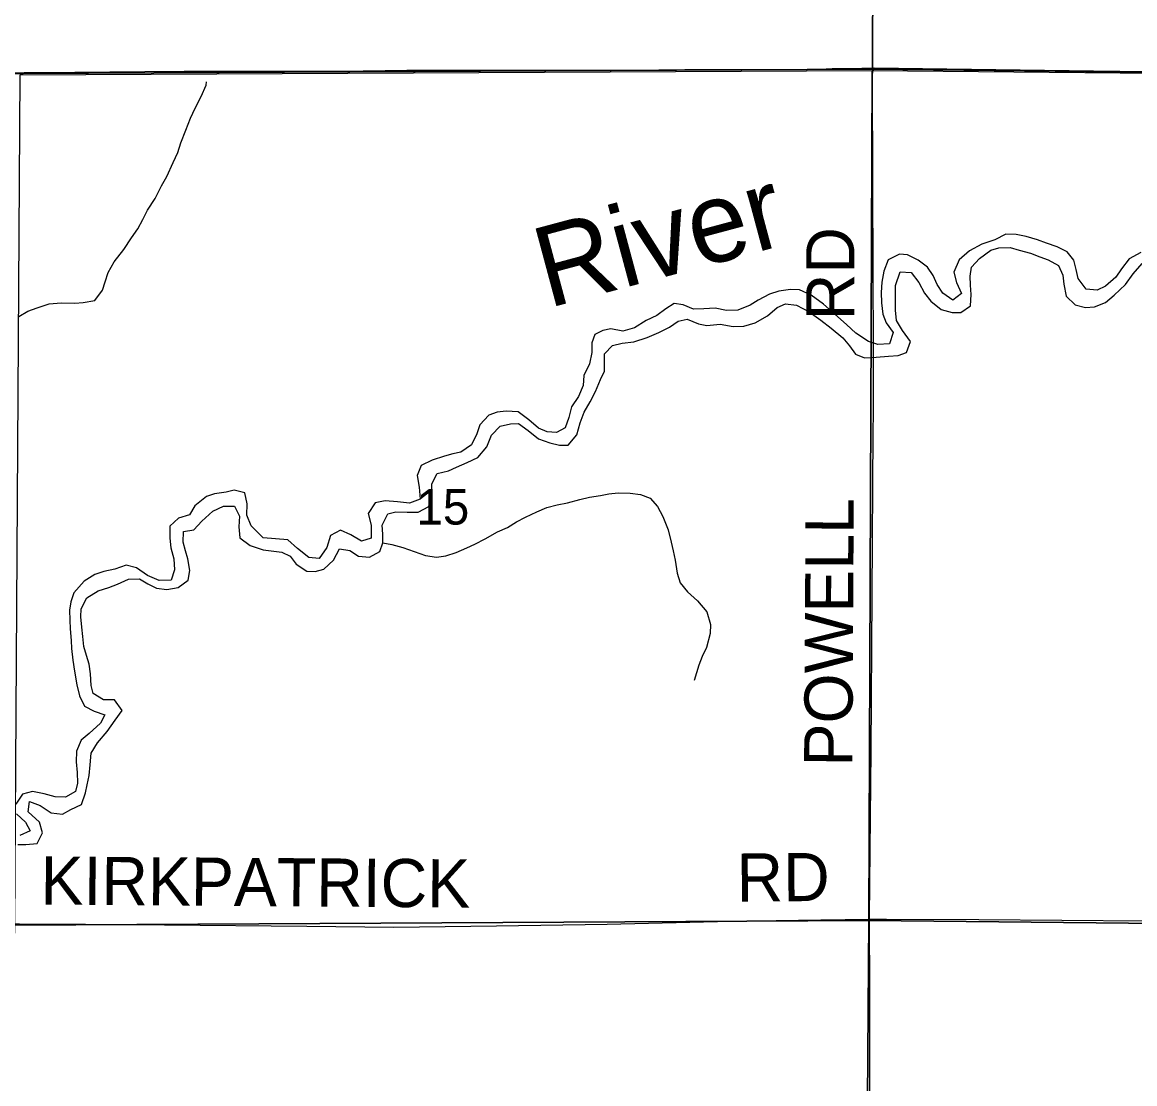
# Model space of a CAD drawing. Extents: x 1584893 to 1934202, y 663575 to 1091909.
# Drawn here: x 1793649 to 1800576, y 978799 to 985411 of the extents above; entities that cross this region are included whole.
import ezdxf

# ---------------------------------------------------------------- set-up
doc = ezdxf.new("R2010")
doc.units = 0
for name, color, linetype in [('GM_X_Adjacent_County', 7, 'Continuous'), ('GM_X_County', 7, 'Continuous'), ('GM_X_County_Road', 7, 'Continuous'), ('GM_X_County_Road_Text', 7, 'Continuous'), ('GM_X_Major_River', 7, 'Continuous'), ('GM_X_Major_River_Text', 7, 'Continuous'), ('GM_X_Minor_River', 7, 'Continuous'), ('GM_X_Section', 7, 'Continuous'), ('GM_X_Section_Text', 7, 'Continuous'), ('GM_X_Township', 7, 'Continuous'), ('GM_X_Township_Road', 7, 'Continuous'), ('GM_X_Township_Road_Text', 7, 'Continuous')]:
    doc.layers.add(name, color=color, linetype=linetype)

msp = doc.modelspace()

# ---------------------------------------------------------------- linework, layer by layer
at = {"layer": 'GM_X_Adjacent_County'}
for points in [[(1798963, 1000817.5), (1798919.4, 995550.1), (1798958.2, 993982), (1798960.7, 990391.9), (1798944.1, 985118.7), (1793655.1, 985091.4), (1790446.1, 985072.3), (1788294.4, 985062.9), (1785879.4, 985048.8), (1785146.5, 985037.7), (1784945.3, 985034.8), (1783032.3, 985018.6), (1777599.8, 984995.7), (1776296.6, 985001.4), (1772301.8, 985036.8), (1771919.4, 985044.5), (1771011.6, 985062.3), (1767040.7, 985145.4), (1761102.7, 985171.2), (1756190.2, 985192.4)], [(1810918.2, 985032.9), (1809553.9, 985051.1), (1805633.6, 985059.6), (1804716.7, 985058.2), (1804440.3, 985060.6), (1804246.1, 985060.1), (1798944.1, 985118.7), (1798960.7, 990391.9), (1798958.2, 993982), (1798919.4, 995550.1), (1798963, 1000817.5)]]:
    msp.add_lwpolyline(points, dxfattribs=at)
at = {"layer": 'GM_X_County'}
msp.add_lwpolyline([(1756190.2, 985192.4), (1761102.7, 985171.2), (1767040.7, 985145.4), (1771011.6, 985062.3), (1771919.4, 985044.5), (1772301.8, 985036.8), (1776296.6, 985001.4), (1777599.8, 984995.7), (1783032.3, 985018.6), (1784945.3, 985034.8), (1785146.5, 985037.7), (1785879.4, 985048.8), (1788294.4, 985062.9), (1790446.1, 985072.3), (1793655.1, 985091.4), (1798944.1, 985118.7), (1804246.1, 985060.1), (1804440.3, 985060.6), (1804716.7, 985058.2), (1805633.6, 985059.6), (1809553.9, 985051.1), (1810918.2, 985032.9)], dxfattribs=at)
at = {"layer": 'GM_X_County_Road'}
for points in [[(1790514.2, 979812.8), (1790957.4, 979819.1), (1791417, 979818.3), (1791958.8, 979812.3), (1792500.1, 979806.5), (1793238.6, 979798.9), (1793632.5, 979795.2), (1794042.8, 979792.3), (1794535.1, 979788.9), (1795421.3, 979779.9), (1795962.8, 979775.5), (1796602.7, 979782.8), (1797291.9, 979794), (1798063.1, 979811), (1798621, 979820.2), (1798925.1, 979823.4)], [(1798925.1, 979823.4), (1799031.3, 979824.5), (1799605.8, 979821.8), (1800639.7, 979814.1), (1801000.7, 979811.3), (1801493.1, 979807.3), (1802559.8, 979796.2), (1804053.2, 979779), (1804213.8, 979777.6)]]:
    msp.add_lwpolyline(points, dxfattribs=at)
at = {"layer": 'GM_X_Major_River'}
for points in [[(1800341.9, 983741.7), (1800273.9, 983748.5), (1800224.6, 983815.3), (1800211.3, 983871.6), (1800195.9, 983928), (1800154.5, 983980.6), (1800092.8, 984011.4), (1800026.9, 984034.2), (1799971.1, 984055), (1799899.2, 984075.9), (1799837.3, 984088.6), (1799773.2, 984091.4), (1799704.7, 984056.1), (1799624.3, 984028.9), (1799547.7, 983987.7), (1799482.9, 983930.3), (1799450, 983854.5), (1799467.2, 983790.1), (1799496.5, 983721.5), (1799443.9, 983680), (1799380.3, 983722.9), (1799346.9, 983777.4), (1799321.5, 983833.9), (1799286.1, 983884.5), (1799228.5, 983929.3), (1799160.8, 983962.2), (1799110.8, 983966.8), (1799040.3, 983931.5), (1799013.4, 983859.6), (1799000.6, 983791.5), (1798997.8, 983727.4), (1798999.1, 983663.2), (1799008.2, 983592.8), (1799027.6, 983538.5), (1799071, 983477.8), (1799050.1, 983407.8), (1798975.9, 983402.7), (1798918.1, 983421.4), (1798840.6, 983474.5), (1798781.1, 983527.3), (1798709.8, 983592.3), (1798638.4, 983655.4), (1798561, 983710.4), (1798489.3, 983743.4), (1798433.2, 983746), (1798361, 983736.8), (1798302.7, 983717.5), (1798232.1, 983680.2), (1798181.7, 983648.7), (1798105.2, 983617.5), (1798035.1, 983616.3), (1797963.2, 983629.2), (1797893, 983626), (1797828.9, 983622.7), (1797765.1, 983651.6), (1797709.1, 983658.2), (1797656.7, 983626.8), (1797600.1, 983585.3), (1797533.6, 983554), (1797461, 983506.7), (1797388.6, 983487.5), (1797314.7, 983500.4), (1797264.5, 983490.9), (1797214.1, 983465.4), (1797195.5, 983413.5), (1797196.8, 983353.3), (1797181.9, 983283.3), (1797145, 983211.5), (1797142.3, 983147.3), (1797113.4, 983079.5), (1797068.6, 983015.8), (1797051.8, 982949.8), (1797029, 982883.9), (1796976.6, 982856.4), (1796918.5, 982859.1), (1796864.7, 982881.8), (1796803.3, 982934.7), (1796737.7, 982983.6), (1796661.7, 982988.5), (1796605.5, 982983.1), (1796555.2, 982963.7), (1796498.5, 982904.1), (1796479.7, 982846.2), (1796446.9, 982778.4), (1796380.3, 982733), (1796330.1, 982723.6), (1796277.8, 982708.1), (1796201.4, 982682.9), (1796132.9, 982649.7), (1796108.1, 982587.8), (1796121.3, 982515.4), (1796126.4, 982441.1), (1796060, 982415.8), (1795986, 982422.7), (1795910, 982429.6), (1795845.8, 982418.3), (1795802.9, 982350.6), (1795822.1, 982278.2), (1795821.1, 982197.9), (1795760.8, 982178.6), (1795695.2, 982217.5)], [(1795811.7, 982079.7), (1795876.2, 982115), (1795894.9, 982169), (1795895.5, 982223.1), (1795890.2, 982277.4), (1795925.1, 982349.2), (1795975.3, 982360.6), (1796045.4, 982359.8), (1796115.4, 982359), (1796180, 982394.3), (1796196.8, 982464.3), (1796199.7, 982536.5), (1796232.5, 982600.3), (1796302.8, 982617.6), (1796353.1, 982639), (1796419.5, 982668.4), (1796486, 982699.7), (1796542.9, 982767.2), (1796571.8, 982839.1), (1796624.5, 982894.6), (1796688.8, 982909.9), (1796738.9, 982911.3), (1796798.5, 982868.5), (1796863.9, 982815.6), (1796933.7, 982790.7), (1796993.7, 982776), (1797047.7, 982777.3), (1797102.6, 982840.9), (1797123.5, 982914.9), (1797148.3, 982982.8), (1797185.1, 983046.5), (1797217.9, 983110.3), (1797248.9, 983186.2), (1797275.5, 983238), (1797274.1, 983288.2), (1797274.8, 983346.4), (1797325.5, 983397.9), (1797385.7, 983411.3), (1797458, 983420.5), (1797540.4, 983447.6), (1797612.9, 983478.8), (1797679.4, 983512.2), (1797733.9, 983549.6), (1797790.1, 983561), (1797859.9, 983532.1), (1797911.8, 983521.5), (1797994, 983530.5), (1798076, 983515.5), (1798142.1, 983518.8), (1798212.4, 983538), (1798289.1, 983583.2), (1798349.8, 983634.7), (1798402.1, 983656.1), (1798470.1, 983649.3), (1798549.7, 983606.3), (1798621.2, 983555.3), (1798686.7, 983504.4), (1798758.1, 983445.3), (1798799.6, 983394.7), (1798837, 983344.1), (1798892.9, 983321.4), (1798967, 983324.5), (1799043.2, 983331.7), (1799103.3, 983335), (1799155.6, 983354.4), (1799180.5, 983422.3), (1799129.2, 983491.1), (1799091.9, 983553.8), (1799086.6, 983618), (1799087.2, 983668.2), (1799085.9, 983720.3), (1799086.5, 983770.5), (1799115.5, 983856.4), (1799183.6, 983851.6), (1799230.9, 983788.8), (1799266.2, 983724.2), (1799305.6, 983673.6), (1799371.1, 983620.7), (1799439, 983603.8), (1799493.1, 983603.2), (1799553.6, 983644.6), (1799558.5, 983714.8), (1799553.2, 983773), (1799551.8, 983829.2), (1799560.5, 983885.3), (1799609.2, 983938.8), (1799679.9, 983990.2), (1799730.2, 984005.6), (1799800.3, 984006.8), (1799856.2, 983992.1), (1799926.1, 983973.2), (1799985.9, 983950.5), (1800037.7, 983931.8), (1800101.4, 983895), (1800128.7, 983834.5), (1800134.1, 983780.2), (1800149.2, 983703.8), (1800204.7, 983651), (1800268.6, 983634.2), (1800324.7, 983637.6), (1800393.1, 983664.9)], [(1800613.1, 983977.2), (1800540.5, 983938), (1800493.7, 983874.3), (1800459.1, 983822.6), (1800394.3, 983767.2), (1800341.9, 983741.7)], [(1800393.1, 983664.9), (1800447.7, 983710.4), (1800518.6, 983777.7), (1800565.5, 983843.4), (1800622.3, 983908.9)], [(1795150.3, 982198.8), (1795075.5, 982274.8), (1795048, 982341.1), (1795050.5, 982411.2), (1795035, 982479.5), (1794969.1, 982496), (1794918.9, 982484.3), (1794846.8, 982472.8), (1794796.6, 982457.1), (1794724.1, 982399.5), (1794691.7, 982343.6), (1794621.4, 982322), (1794569, 982272.3), (1794568.5, 982198.1), (1794574, 982138), (1794593.5, 982069.7), (1794597, 981999.5), (1794576.5, 981935.5), (1794502.4, 981934), (1794428.6, 981964.6), (1794360.9, 982013.2), (1794297, 982029.7), (1794226.7, 982004.1), (1794156.5, 981990.6), (1794102.3, 981970.9), (1794034, 981929.3), (1793971.4, 981857.6), (1793952.9, 981801.6), (1793944.5, 981749.5), (1793946.1, 981687.4), (1793947.7, 981633.2), (1793953.1, 981561), (1793956.8, 981510.9), (1793964.2, 981436.7), (1793975.7, 981368.5), (1793989.1, 981284.2), (1794006.6, 981215.9), (1794036.2, 981151.6), (1794098, 981119.1), (1794163.9, 981096.6), (1794137.5, 981044.6), (1794066.9, 980981), (1794016.6, 980939.2), (1793988, 980871.3), (1793985.5, 980805.2), (1793991, 980737), (1793992.6, 980670.8), (1793980.2, 980618.8), (1793917.8, 980583.2), (1793853.8, 980585.6), (1793785.9, 980604.1), (1793713.9, 980618.7), (1793651.7, 980603.1), (1793609.2, 980541.2)], [(1793621.4, 980288.6), (1793671.4, 980290.2), (1793741.5, 980295.8), (1793776, 980361.7), (1793756.5, 980427.9), (1793686.9, 980492.6), (1793695.4, 980556.7), (1793761.3, 980532.1), (1793829, 980487.6), (1793901, 980479), (1793951.3, 980506.8), (1794017.6, 980538.4), (1794044.1, 980610.3), (1794054.5, 980660.4), (1794065, 980718.4), (1794071.5, 980786.5), (1794078, 980858.7), (1794118.5, 980922.5), (1794179.1, 980992.2), (1794227.7, 981064.1), (1794272.2, 981123.9), (1794224.6, 981190.3), (1794154.6, 981190.8), (1794090.8, 981229.4), (1794079.2, 981279.6), (1794073.7, 981351.8), (1794066.1, 981411.9), (1794048.5, 981466.2), (1794032.9, 981522.4), (1794027.4, 981584.6), (1794019.8, 981642.8), (1794014.3, 981706.9), (1794016.7, 981757), (1794051.2, 981824.9), (1794121.6, 981868.5), (1794187.8, 981890.1), (1794242, 981911.8), (1794310.3, 981941.4), (1794378.4, 981944.9), (1794432.2, 981912.5), (1794486.1, 981886), (1794550.1, 981877.6), (1794620.2, 981891.1), (1794682.6, 981936.8), (1794693.1, 981996.8), (1794679.6, 982069.1), (1794666, 982119.3), (1794650.3, 982173.5), (1794652.9, 982239.7), (1794717, 982249.2), (1794767.4, 982303), (1794836, 982366.6), (1794902.2, 982396.2), (1794970.3, 982395.8), (1795001.9, 982335.4), (1794997.4, 982267.3), (1795004.9, 982199.1), (1795068.6, 982152.6), (1795148.8, 982125.1)], [(1795695.2, 982217.5), (1795631.4, 982246.3), (1795569, 982214.9), (1795546, 982139), (1795497.2, 982071.3), (1795433.1, 982076.1), (1795363.7, 982133.1), (1795302.2, 982186), (1795150.3, 982198.8)], [(1795148.8, 982125.1), (1795265.3, 982110.2), (1795317.1, 982085.5), (1795354.5, 982034.9), (1795422.1, 981992), (1795472.2, 981989.4), (1795526.4, 982004.8), (1795587.1, 982060.3), (1795624.1, 982132), (1795688, 982121.3), (1795743.7, 982084.5), (1795811.7, 982079.7)], [(1793612.8, 980481.1), (1793670.5, 980428.5), (1793698.1, 980374.2), (1793633.8, 980344.6)]]:
    msp.add_lwpolyline(points, dxfattribs=at)
at = {"layer": 'GM_X_Minor_River'}
for points in [[(1793627.9, 983577.7), (1793684.2, 983611.3), (1793742.4, 983633), (1793816.6, 983656.5), (1793892.7, 983664), (1793976.8, 983661.4), (1794028.9, 983665.1), (1794101.1, 983678.6), (1794149.6, 983742.4), (1794166, 983794.4), (1794184.4, 983852.4), (1794221, 983918.3), (1794281.6, 983996), (1794330.2, 984067.8), (1794368.6, 984123.7), (1794401.1, 984181.6), (1794429.5, 984239.5), (1794476.1, 984313.3), (1794516.7, 984391.2), (1794549.2, 984449.1), (1794589.9, 984537), (1794618.4, 984598.9), (1794636.9, 984658.9), (1794667.5, 984738.9), (1794696.1, 984812.8), (1794726.5, 984874.8), (1794763.1, 984948.7), (1794793.7, 985018.6), (1794797.1, 985039.8)], [(1795894.9, 982169), (1795950.8, 982158.3), (1796018.7, 982139.4), (1796090.5, 982114.5), (1796160.3, 982089.7), (1796228.3, 982078.8), (1796286.5, 982088.2), (1796350.8, 982107.5), (1796417.3, 982136.8), (1796467.6, 982160.3), (1796532.1, 982193.6), (1796608.7, 982236.8), (1796671.1, 982264.2), (1796727.6, 982299.7), (1796782.1, 982329.1), (1796852.5, 982360.4), (1796914.9, 982387.7), (1796979.2, 982405), (1797043.5, 982418.3), (1797121.8, 982437.4), (1797182.1, 982452.8), (1797250.3, 982464), (1797302.5, 982473.4), (1797360.7, 982478.8), (1797434.8, 982477.9), (1797498.8, 982469.2), (1797558.6, 982446.4), (1797604, 982393.7), (1797637.3, 982333.1), (1797670.4, 982248.5), (1797689.5, 982172), (1797702.9, 982117.7), (1797714.2, 982059.4), (1797727.3, 981979), (1797746.6, 981918.6), (1797792, 981863.9), (1797853.4, 981807), (1797912.7, 981738.1), (1797933.8, 981659.6), (1797933.2, 981603.5), (1797910.1, 981515.5), (1797883.4, 981459.6), (1797862.7, 981405.7), (1797833.6, 981311.8)]]:
    msp.add_lwpolyline(points, dxfattribs=at)
at = {"layer": 'GM_X_Section'}
for points in [[(1798941.7, 985111.2), (1798921.1, 979816.2), (1793602.5, 979786.3), (1793636.7, 985083.2)], [(1798941.7, 985111.2), (1804234.6, 985059.6), (1804175.9, 979761.7), (1798921.1, 979816.2)], [(1793602.5, 979786.3), (1798921.1, 979816.2), (1798880.2, 974507.2), (1793492.3, 974493.9)], [(1798921.1, 979816.2), (1804175.9, 979761.7), (1804173.2, 974476.5), (1798880.2, 974507.2)]]:
    msp.add_lwpolyline(points, close=True, dxfattribs=at)
at = {"layer": 'GM_X_Township'}
msp.add_lwpolyline([(1783032.3, 985018.6), (1784945.3, 985034.8), (1785146.5, 985037.7), (1785879.4, 985048.8), (1788294.4, 985062.9), (1790446.1, 985072.3), (1793655.1, 985091.4), (1798944.1, 985118.7), (1804246.1, 985060.1), (1804440.3, 985060.6), (1804716.7, 985058.2), (1805633.6, 985059.6), (1809553.9, 985051.1), (1809489.7, 979763.3), (1809470.3, 974481.1), (1809409.4, 966524.3)], dxfattribs=at)
at = {"layer": 'GM_X_Township_Road'}
for points in [[(1790448.7, 985077.4), (1790503.7, 985078), (1790851.5, 985080.6), (1791060.9, 985081.7), (1791234.2, 985084), (1791371.5, 985085.1), (1791538.3, 985086.2), (1791749.8, 985086.3), (1791918.8, 985087.4), (1792081.2, 985088.5), (1792183.7, 985089.6), (1792386.4, 985090.8), (1792607.7, 985090.8), (1793100.5, 985093.1), (1793428.6, 985095.4), (1793662, 985097.3)], [(1793662, 985097.3), (1793975.8, 985099.9), (1794411.9, 985103.3), (1794657.2, 985106.6), (1794869.4, 985106.8), (1795017.1, 985106), (1795230.6, 985105.6), (1795509.5, 985106.5), (1795772.2, 985107.9), (1796044.9, 985111.3), (1796573.6, 985112.5), (1796919.2, 985112.6), (1797199.4, 985112.7), (1797451.2, 985112.7), (1797774.9, 985116.1), (1797964.6, 985116.1), (1798299.9, 985116.2), (1798541.3, 985119.5), (1798654.4, 985120.4), (1798693.1, 985121.8), (1798795, 985123.4), (1798955.8, 985126.6)], [(1798949.6, 983379.8), (1798947.1, 983858.7), (1798945.2, 984400.1), (1798943.1, 985070.5), (1798944.2, 985085.9), (1798945.2, 985100), (1798947.8, 985111.2), (1798951.7, 985120.2), (1798955.8, 985126.6)], [(1798955.8, 985126.6), (1799254.8, 985122.9), (1800319.5, 985108.4), (1800810.4, 985101.5), (1800941.6, 985100.4), (1801352.3, 985096.8), (1801598.7, 985094), (1802173.7, 985088.9), (1802436.6, 985086.8), (1802962.4, 985084.2), (1803675.3, 985073.1), (1803882, 985069.9), (1804248.7, 985067.6)], [(1798925.1, 979823.4), (1798925, 979839.1), (1798934.5, 980872.7), (1798941.1, 981840.7), (1798948.2, 982857.9), (1798949.7, 982977.7), (1798950.4, 983218.9), (1798949.6, 983379.8)], [(1798948, 978516.4), (1798946.3, 978517.6), (1798940, 978523.5), (1798935.5, 978529.3), (1798931.2, 978536.1), (1798928, 978543.4), (1798925.8, 978551.5), (1798924.2, 978560.8), (1798923.4, 978570.5), (1798923.1, 978592), (1798924.2, 978666.3), (1798926.3, 978756.2), (1798927.7, 979379.7), (1798925.1, 979823.4)]]:
    msp.add_lwpolyline(points, dxfattribs=at)

# ---------------------------------------------------------------- texts
at = {"layer": 'GM_X_County_Road_Text'}
for s, rotation, p in [('RD', 0.49366, (1798098.3, 979933)), ('KIRKPATRICK', 359.59266, (1793762.3, 979915.5))]:
    msp.add_text(s, height=300, rotation=rotation, dxfattribs=at).set_placement(p)
at = {"layer": 'GM_X_Major_River_Text'}
msp.add_text('River', height=500.1, rotation=15.01455, dxfattribs=at).set_placement((1796922.3, 983628.5))
at = {"layer": 'GM_X_Section_Text'}
msp.add_text('15', height=221, rotation=0.00001, dxfattribs=at).set_placement((1796103.9, 982282.1))
at = {"layer": 'GM_X_Township_Road_Text'}
for s, rotation, p in [('RD', 90, (1798830.5, 983555)), ('POWELL', 89.66143, (1798817.2, 980774.6))]:
    msp.add_text(s, height=300, rotation=rotation, dxfattribs=at).set_placement(p)

doc.saveas('drawing.dxf')
